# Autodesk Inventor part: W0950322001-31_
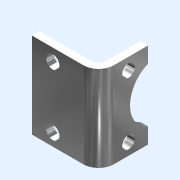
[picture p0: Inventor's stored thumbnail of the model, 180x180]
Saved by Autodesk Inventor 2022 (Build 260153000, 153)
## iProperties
Part Number: W0950322001-31_
Material: Generico
Catalog Web Link: www.cadenas.de
Description: FOOT - MODEL A_-
Vendor: METALWORK
Document SubType Name: Modeling
Designer: partserver
Manufacturer: METALWORK
Mass: 8.43033 g
Surface Area: 53.8353 cm^2
Volume: 8.43033 cm^3
Density: 1 g/cm^3
Appearance: Alluminio - Piatto
Category: PARTsolutions
Company: METALWORK
PSOL_IDENT_0: {$CADENAS_DATA\23d-libs\metalwork\actuators\parts\foot.prj},176 {VTYP=3D},{NB=W0950322001-31_},{LINA=
PSOL_IDENT_1: W0950322001},{NN=FOOT - MODEL A_},{DATE=18.06.2021 08:06:10},{GEOMDATE=02.08.2018 11:04:45},{VERSION=
PSOL_IDENT_2: },{LINEID=640},{WBVAR=},{WBNUMERIC=}  {NB=W0950322001-31_},{LINA=W0950322001},{KT=DUMMY},{IDNR=},{CO
PSOL_IDENT_3: DE=W0950322001},{VER=31},{V1=3},{DI=32},{A=45},{B=35.0},{C=32},{D=24.000},{XS=0.000},{AB=0.000},{AH=
PSOL_IDENT_4: 0.000},{AO=0.000},{AT=0.000},{AU=0.000},{NH=0.000},{TR=0.000},{US=0.000},{R=0.000},{E=7.0},{XA=0.000
PSOL_IDENT_5: },{SA=0.000},{H=32.0},{N=74.5},{N1=92.5},{S=4},{WG=76},{R1=15.500},{BH=26.000},{ND=6.000},{TG=32.500
PSOL_IDENT_6: },{DH=6.600},{SL=16.000},{UH=0.000},{H1=0.000},{H2=0.000}
NB: W0950322001-31_
NN: FOOT - MODEL A_
NBSYN: $CODE.-$VER._
LINA: W0950322001
CATALOG: Metalwork
CODE: W0950322001
VER: 31
V1: 3
DI: 32
A: 45
B: 35
C: 32
D: 24
XS: 0
AB: 0
AH: 0
AO: 0
AT: 0
AU: 0
NH: 0
TR: 0
US: 0
R: 0
E: 7
XA: 0
SA: 0
H: 32
N: 74.5
N1: 92.5
S: 4
WG: 76
R1: 15.5
BH: 26
ND: 6
TG: 32.5
DH: 6.6
SL: 16
UH: 0
H1: 0
H2: 0
SUPPLIER: METALWORK
ARTICLENO: W0950322001-31_
BOMINFO: W0950322001
CREATOR: CADENAS GmbH
Title: W0950322001
Author: Cadenas PARTsolutions
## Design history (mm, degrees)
sketch "Sketch_1"
  geometry: L1 (8, -32)-(35, -32); L2 (35, -32)-(35, -28); L3 (35, -28)-(8, -28); L4 (4, -24)-(4, -6); L5 (4, -6)-(0, -6); L6 (0, -6)-(0, -24); A1 r 8 centre (8, -24) between (0, -24) and (8, -32); A2 r 4 centre (8, -24) between (4, -24) and (8, -28)
  constraints: 12 end point, 4 point on circle, 2 centre point
extrude "Extrusion1" join sketch "Sketch_1" stored distance "d0" = 45; taper "d1" = 0 deg
sketch "Sketch_2"
  geometry: C1 r 15.5 at (0, 0); 1 further point
  constraints: 1 centre point
extrude "Extrusion2" cut sketch "Sketch_2" distance "d2" = 4; taper "d3" = 0 deg
sketch "Sketch_3"
  geometry: C1 r 3.5 at (-24, -16); 1 further point
  constraints: 1 centre point
extrude "Extrusion3" cut sketch "Sketch_3" distance "d4" = 32; taper "d5" = 0 deg
sketch "Sketch_4"
  geometry: C1 r 3.5 at (-24, 16); 1 further point
  constraints: 1 centre point
extrude "Extrusion4" cut sketch "Sketch_4" distance "d6" = 32; taper "d7" = 0 deg
sketch "Sketch5"
  geometry: 1 further point
hole "Hole1" sketch "Sketch5" at (6.25, 7.75) diameter "d8" = 6.6; stored, may be unused: countersink angle "d12" = 90 deg, drill point angle "d14" = 0 deg; dims "d9" = 6, "d10" = 4, "d11" = 2, "d13" = 4
sketch "Sketch6"
  geometry: 1 further point
hole "Hole2" sketch "Sketch6" at (38.75, 7.75) diameter "d15" = 6.6; stored, may be unused: countersink angle "d19" = 90 deg, drill point angle "d21" = 0 deg; dims "d16" = 6, "d17" = 4, "d18" = 2, "d20" = 4
node "body_XY"
node "body_YZ"
node "body_ZX"
node "body_X"
node "body_Y"
node "body_Z"
node "body_Center"
node "screws_1_XY"
node "screws_1_YZ"
node "screws_1_ZX"
node "screws_1_X"
node "screws_1_Y"
node "screws_1_Z"
node "screws_1_Center"
node "screws_2_XY"
node "screws_2_YZ"
node "screws_2_ZX"
node "screws_2_X"
node "screws_2_Y"
node "screws_2_Z"
node "screws_2_Center"
body "Solid1"
other parameters: "d22" = 0, "d23" = 0, "d24" = 0
